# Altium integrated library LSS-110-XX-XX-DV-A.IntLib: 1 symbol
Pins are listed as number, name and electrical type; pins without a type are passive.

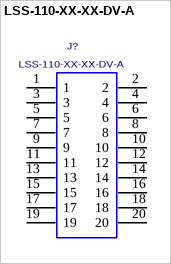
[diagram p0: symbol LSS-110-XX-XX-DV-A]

## LSS-110-XX-XX-DV-A
designator J?
0.635MM TERMINAL/SOCKET COMB, 20 PINS.; MANUFACTURER: SAMTEC
footprint LSS-110-XX-XX-DV-A
pins: 1, 2, 3, 4, 5, 6, 7, 8, 9, 10, 11, 12, 13, 14, 15, 16, 17, 18, 19, 20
